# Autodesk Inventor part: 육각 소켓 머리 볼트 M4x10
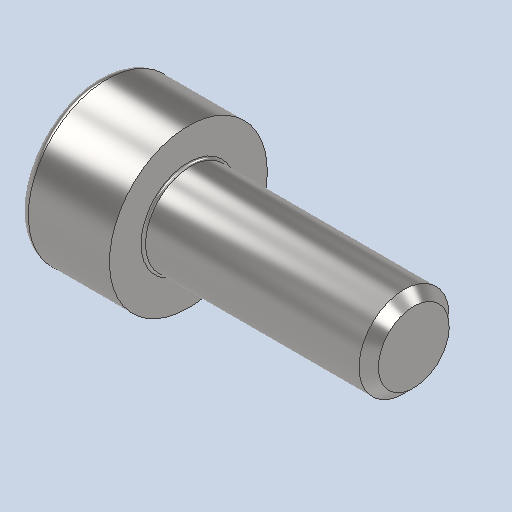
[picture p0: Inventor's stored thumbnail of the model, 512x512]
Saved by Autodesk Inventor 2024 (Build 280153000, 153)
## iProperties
Created: 2024-11
Part Number: 육각 소켓 머리 볼트 M4x10
Material: 강철, 연강
Description: 6각머리 태핑 나사
Document SubType Name: Modeling
Designer: user
Density: 7.85 g/cm^3
Appearance: 기본값
Author: jhkim
Sending System: Autodesk Inventor 2025
Preprocessor: ST-DEVELOPER v20
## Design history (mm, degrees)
node "육각 소켓 머리 볼트 M4x101"
node "솔리드1"
body "Solid1"
